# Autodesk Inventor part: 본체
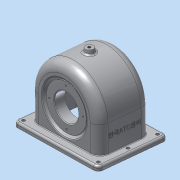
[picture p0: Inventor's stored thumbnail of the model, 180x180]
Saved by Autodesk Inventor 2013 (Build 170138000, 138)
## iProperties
Created: 2015-09
Part Number: 본체
Material: 알루미늄 6061
Document SubType Name: Modeling
Designer: Administrator
Density: 2.71 g/cm^3
Mass: 654.453 g
Surface Area: 930.523 cm^2
Volume: 241.496 cm^3
Author: Administrator
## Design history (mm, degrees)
sketch "스케치1"
  geometry: L1 (-57, 0)-(-57, -40); L2 (-57, -40)-(57, -40); L3 (57, 0)-(57, -40); A1 r 57 centre (0, 0) between (-40.608, -40) and (57, 0); A2 r 57 centre (0, 0) between (-57, 0) and (-40.608, -40); A3 r 57 centre (0, 0) between (57, 0) and (-57, 0); 1 further point
  constraints: 6 end point, 6 point on circle, 4 tangent, 3 centre point, 2 perpendicular, 1 coincident, 1 point on line, 1 vertical
  dimensions: "d0" = 57 radius of A1; "d1" = 40 distance of L1.start L1.end
extrude "돌출1" new body sketch "스케치1" stored distance "d2" = 77; taper "d3" = 0 deg
node "작업 평면1"
sketch "스케치4"
  geometry: C1 r 6 at (-57, -38.5); 1 further point
  constraints: 1 centre point, 1 coincident
  dimensions: "d9" = 12 diameter of C1
extrude "돌출3" join sketch "스케치4" stored distance "d10" = 7; taper "d11" = 10 deg
feature "쉘1" dims "d12" = 5
sketch "스케치5"
  geometry: L1 (127, -90.5)-(-13, -90.5); L2 (-13, -90.5)-(-13, 13.5); L3 (-13, 13.5)-(127, 13.5); L4 (127, 13.5)-(127, -90.5); L5 (127, -90.5)-(-13, 13.5); L6 (-13, -90.5)-(127, 13.5); 1 further point
  constraints: 12 end point, 2 midpoint, 2 parallel, 1 horizontal, 1 perpendicular
  dimensions: "d13" = 140 distance of L2.end L3.end; "d14" = 104 distance of L1.end L2.end
extrude "돌출4" join sketch "스케치5" distance "d15" = 7; taper "d16" = 0 deg
sketch "스케치6"
  geometry: L1 (5, 5)-(5, 72) reference; L2 (5, 72)-(109, 72) reference; L3 (109, 72)-(109, 5) reference; L4 (109, 5)-(5, 5) reference; 2 further points
  constraints: 1 other
extrude "돌출5" cut sketch "스케치6" stored distance "d17" = 7; taper "d18" = 0 deg
node "작업 평면2"
sketch "스케치9"
  geometry: C1 r 28 at (0, 0); 1 further point
  constraints: 1 centre point, 1 coincident
  dimensions: "d20" = 56 diameter of C1
extrude "돌출6" join sketch "스케치9" stored distance "d21" = 7; taper "d22" = 40 deg
sketch "스케치15"
  geometry: L1 (28, 19.5)-(39.747, 33.5) reference; L2 (57, 38.5)-(0, 38.5) reference; L3 (33, 33.237)-(37.416, 38.5); L4 (0, 0)-(0, 38.5); L5 (33, 33.237)-(33, 35.5); L6 (33, 35.5)-(0, 35.5); L7 (0, 38.5)-(37.416, 38.5)
  constraints: 10 end point, 2 parallel, 2 perpendicular, 2 point on line
  dimensions: "d38" = 5 distance between parallel lines of L1 L3; "d39" = 33 distance of L5.end L6.end; "d40" = 3 distance between parallel lines of L2 L6
revolve "회전2" sketch "스케치15" stored, may be unused: angle "d41" = 90 deg
sketch "스케치16"
  geometry: C1 r 20 at (0, 0); 1 further point
  constraints: 1 centre point, 1 coincident
  dimensions: "d42" = 40 diameter of C1
extrude "돌출9" cut sketch "스케치16" stored distance "d43" = 1; taper "d44" = 0 deg
sketch "스케치17"
  geometry: C1 r 31 at (0, 0); 1 further point
  constraints: 1 centre point, 1 coincident
  dimensions: "d45" = 62 diameter of C1
extrude "돌출10" join sketch "스케치17" distance "d46" = 10; taper "d47" = 0 deg
sketch "스케치18"
  geometry: C1 r 20 at (0, 0); 1 further point
  constraints: 1 centre point, 1 coincident
  dimensions: "d48" = 40 diameter of C1
extrude "돌출11" cut sketch "스케치18" stored distance "d49" = 10; taper "d50" = 0 deg
sketch "스케치19"
  geometry: 2 further points
  constraints: 1 vertical alignment
  dimensions: "d51" = 28 distance of point (0, 0) point (0, 28)
hole "구멍1" sketch "스케치19" at (0, 28) diameter "d52" = 2.459; stored, may be unused: countersink angle "d56" = 90 deg, drill point angle "d58" = 118 deg; dims "d53" = 7, "d54" = 4, "d55" = 2, "d57" = 9
sketch "스케치20"
  geometry: 2 further points
  constraints: 1 vertical alignment
  dimensions: "d62" = 24 distance of point (0, 0) point (0, 24)
hole "구멍2" sketch "스케치20" at (0, 24) diameter "d63" = 2.459; stored, may be unused: countersink angle "d67" = 90 deg, drill point angle "d69" = 118 deg; dims "d64" = 6, "d65" = 4, "d66" = 2, "d68" = 8
sketch "스케치22"
  geometry: L1 (90.5, -47)-(-13.5, -47) reference; L2 (0, -40)-(0, 0) reference; 2 further points
  constraints: 1 other
  dimensions: "d80" = 30 distance from line of L1 point (38.5, -17); "d81" = 38.5 distance from line of L2 point (38.5, -17)
feature "엠보싱1" sketch "스케치22" dims "d13" = 140, "d14" = 104, "d82" = 0.5, "d83" = 0
fillet "모깎기1" dims "d87" = 14
fillet "모깎기2" dims "d88" = 7
sketch "스케치24"
  geometry: L1 (-5, -5.5)-(119, -5.5); L2 (119, -5.5)-(119, 82.5); L3 (119, 82.5)-(-5, 82.5); L4 (-5, 82.5)-(-5, -5.5); L5 (-5, -5.5)-(119, 82.5); L6 (119, -5.5)-(-5, 82.5); 7 further points
  constraints: 12 end point, 4 coincident, 4 midpoint, 2 parallel, 1 horizontal, 1 perpendicular
  dimensions: "d89" = 124 distance of L3.end L2.end; "d90" = 88 distance of L2.end L1.end
hole "구멍4" sketch "스케치24" at (-5, 38.5), (-5, -5.5), (-5, 82.5), (119, 82.5), (119, -5.5), (119, 38.5) diameter "d91" = 5; stored, may be unused: countersink angle "d95" = 90 deg, drill point angle "d97" = 118 deg; dims "d92" = 6, "d93" = 4, "d94" = 2, "d96" = 8
fillet "모깎기3" dims "d98" = 3
fillet "모깎기5" dims "d100" = 3
fillet "모깎기6" dims "d101" = 9
fillet "모깎기7" dims "d102" = 3
fillet "모깎기8" dims "d103" = 1
fillet "모깎기9" dims "d104" = 0.5
chamfer "모따기1" distance "d105" = 1; stored, may be unused: second distance "d106" = 2, angle "d107" = 45 deg
sketch "스케치27"
  geometry: L1 (58, 1.805)-(52, 2.862) reference; L2 (58, -1.805)-(52, -2.862) reference; L3 (58, 1.805)-(58, -1.805) reference; L4 (58, 0)-(51.888, 0); L5 (58, 0)-(58, 1.805); L6 (58, 1.805)-(52, 2.862); L7 (52, 2.862)-(52, 0); L8 (58, 0)-(52, 0); 1 further point
  constraints: 10 end point, 3 perpendicular, 2 collinear, 1 midpoint, 1 point on line
revolve "회전3" sketch "스케치27" stored, may be unused: angle "d122" = 90 deg
sketch "스케치28"
  geometry: 1 further point
hole "구멍7" sketch "스케치28" at (0, 0) diameter "d123" = 4.459; stored, may be unused: countersink angle "d127" = 82 deg, drill point angle "d129" = 118 deg; dims "d124" = 6, "d125" = 3.023, "d126" = 2, "d128" = 8
node "솔리드1"
pattern_circular "원형 패턴1" dims angle "d60" = 360 deg
pattern_circular "원형 패턴2" dims angle "d71" = 360 deg
node "투영된 루프1"
other parameters: "d19" = 14
